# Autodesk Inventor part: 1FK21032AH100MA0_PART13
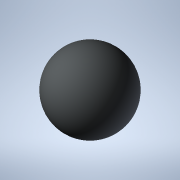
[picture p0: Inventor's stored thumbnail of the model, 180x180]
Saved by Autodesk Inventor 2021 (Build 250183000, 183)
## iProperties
Created: 2025-04
Part Number: 1FK21032AH100MA0_PART13
Material: Generic
Catalog Web Link: www.3dfindit.com
Description: -Servo synchronous motor
Document SubType Name: Modeling
Designer: psAdmin
Mass: 0.113097 g
Surface Area: 1.13097 cm^2
Volume: 0.113097 cm^3
Density: 1 g/cm^3
Appearance: PSOLRGB-212-217-219
Category: PARTsolutions
Title: 1FK21032AH100MA0_PART13
Author: Cadenas PARTsolutions
Comments: Servo synchronous motor
Sending System: PARTsolutions
Preprocessor: ST-DEVELOPER v19.3
PSOL_IDENT_0: {$CADENAS_DATA/23d-libs/siemens_ag/_cat_/12/33/1fk21032ah100ma0.prj},216 {VTYP=3D},{NB=1FK21032AH100
PSOL_IDENT_1: MA0_PART13},{LINA=1FK21032AH100MA0_PART13},{NN=1FK21032AH100MA0_PART13},{NOPRJ=TRUE},{DATE=19.08.202
PSOL_IDENT_2: 5 14:00:27},{GEOMDATE=30.07.2025 02:02:58},{VERSION=},{LINEID=10},{WBVAR=},{WBNUMERIC=}  {NB=1FK2103
PSOL_IDENT_3: 2AH100MA0_PART13},{LINA=1FK21032AH100MA0_PART13},{KT=DUMMY},{PREVIEW=../../../_pool_/d3/78/p_d211_xx
PSOL_IDENT_4: _00934j.png},{DESCSHORT=SIMOTICS S-1FK2 HD, SINAMICS S210 3AC 400V-480V, 0.59 Nm, 4500 rpm},{DESCLON
PSOL_IDENT_5: G=SIMOTICS S-1FK2 HD servo motor M0=0.64 Nm; PN = 0.28 kW at nN=4500 rpm (380-480 V); PN = 0.167 kW
PSOL_IDENT_6: at nN=2500 rpm (200-240 V); with holding brake; degree of protection IP64; cylindrical shaft D14 x 3
PSOL_IDENT_7: 0 mm; absolute encoder 22-bit + 12-bit multiturn (encoder AM22DQC); with OCC interface; plug size M1
PSOL_IDENT_8: 7, rotatable; SIMOTICS S-1FK2 servomotorfor a wide range of uses in industrial environments. SIMOTIC
PSOL_IDENT_9: S S‑1FK2 servomotors are compact synchronous motors with a high dynamic performance that set themsel
PSOL_IDENT_10: ves apart as a result of their high power density, degree of protection and overload capability. The
PSOL_IDENT_11: motors are available in two variants: as High Dynamic variant (highest dynamic performance as a res
PSOL_IDENT_12: ult of the low intrinsic moment of inertia for applications demanding a high dynamic performance wit
PSOL_IDENT_13: h low moved masses) - and as Compact variant (precise and stable closed-loop control for medium up t
PSOL_IDENT_14: o large moved masses as a result of a medium intrinsic moment of inertia). SIMOTICSS‑1FK2 servomotor
PSOL_IDENT_15: s fully exploit their strengths in a system with the SINAMICSS210 frequency converter and simple con
PSOL_IDENT_16: nection using the one cable connection (OCC). Advantages include the short control and positioning t
PSOL_IDENT_17: imes, fast and precise correction of disturbing quantities as well as stable control with a high dyn
PSOL_IDENT_18: amic performance. The servo motors can be configured to address a wide range of requirements. For ex
PSOL_IDENT_19: ample with and without holding brake, IP64 or IP65 degree of protection, singleturn or multiturn abs
PSOL_IDENT_20: olute encoders - to name just a few. Further, the servomotors are available in different shaft heigh
PSOL_IDENT_21: ts extending from 20 to 100. A shaft sealing ring is available to achieve an IP65 degree of protecti
PSOL_IDENT_22: on and for subsequent mounting at the motor or as spare part. SIMOTICS - the optimum motor for each
PSOL_IDENT_23: and every motion control application.},{INTNO=195125315563},{SUPPLIERALTNO=1FK2103-2AH10-0MA0},{MANU
PSOL_IDENT_24: ID=1FK21032AH100MA0},{MANUNAME=Siemens},{MANUTYPEDESC=SYNCHRONOUS MOTOR 1FK2 HD 0,64 NM},{AAU732=SIM
PSOL_IDENT_25: OTICS},{AAO057=S-1FK2},{AAU734=SIMOTICS S-1FK2 HD servo motor M0=0.64 Nm; PN = 0.28 kW at nN=4500 rp
PSOL_IDENT_26: m (380-480 V); PN = 0.167 kW at nN=2500 rpm (200-240 V); with holding brake; degree of protection IP
PSOL_IDENT_27: 64; cylindrical shaft D14 x 30 mm; absolute encoder 22-bit + 12-bit multiturn (encoder AM22DQC); wit
PSOL_IDENT_28: h OCC interface; plug size M17, rotatable;},{AAW338=SYNCHRONOUS MOTOR 1FK2 HD 0,64 NM},{AAO742=SIMOT
PSOL_IDENT_29: ICS},{AAO663=4034106444723},{NOCUPEROU=1},{PRICEQUANTITY=1},{QUANTITYMIN=1},{QUANTITYINT=1},{CTN=850
PSOL_IDENT_30: 15100},{COO=RO},{AAO676=1FK2103-2AH10-0MA0},{AAO677=Siemens AG},{ORDERUNIT=C62},{CONTENTUNIT=C62}
NB: 1FK21032AH100MA0_PART13
NT: Servo synchronous motor
NBSYN: $MANUID._PART13
LINA: 1FK21032AH100MA0_PART13
CATALOG: SIEMENS
PREVIEW: ../../../_pool_/d3/78/p_d211_xx_00934j.png
DESCSHORT: SIMOTICS S-1FK2 HD, SINAMICS S210 3AC 400V-480V, 0.59 Nm, 4500 rpm
DESCLONG: SIMOTICS S-1FK2 HD servo motor M0=0.64 Nm; PN = 0.28 kW at nN=4500 rpm (380-480 V); PN = 0.167 kW at nN=2500 rpm (200-240 V); with holding brake; degree of prot
INTNO: 195125315563
SUPPLIERALTNO: 1FK2103-2AH10-0MA0
MANUID: 1FK21032AH100MA0
MANUNAME: Siemens
MANUTYPEDESC: SYNCHRONOUS MOTOR 1FK2 HD 0,64 NM
AAU732: SIMOTICS
AAO057: S-1FK2
AAU734: SIMOTICS S-1FK2 HD servo motor M0=0.64 Nm; PN = 0.28 kW at nN=4500 rpm (380-480 V); PN = 0.167 kW at nN=2500 rpm (200-240 V); with holding brake; degree of prot
AAW338: SYNCHRONOUS MOTOR 1FK2 HD 0,64 NM
AAO742: SIMOTICS
AAO663: 4034106444723.0
NOCUPEROU: 1
PRICEQUANTITY: 1
QUANTITYMIN: 1
QUANTITYINT: 1
CTN: 85015100
COO: RO
ARTICLENO: 1FK21032AH100MA0_PART13
BOMINFO: 1FK21032AH100MA0_PART13
CREATOR: CADENAS GmbH
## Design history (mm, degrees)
feature "2025_04_17_15_06_16_0705"
body "Solid1"
